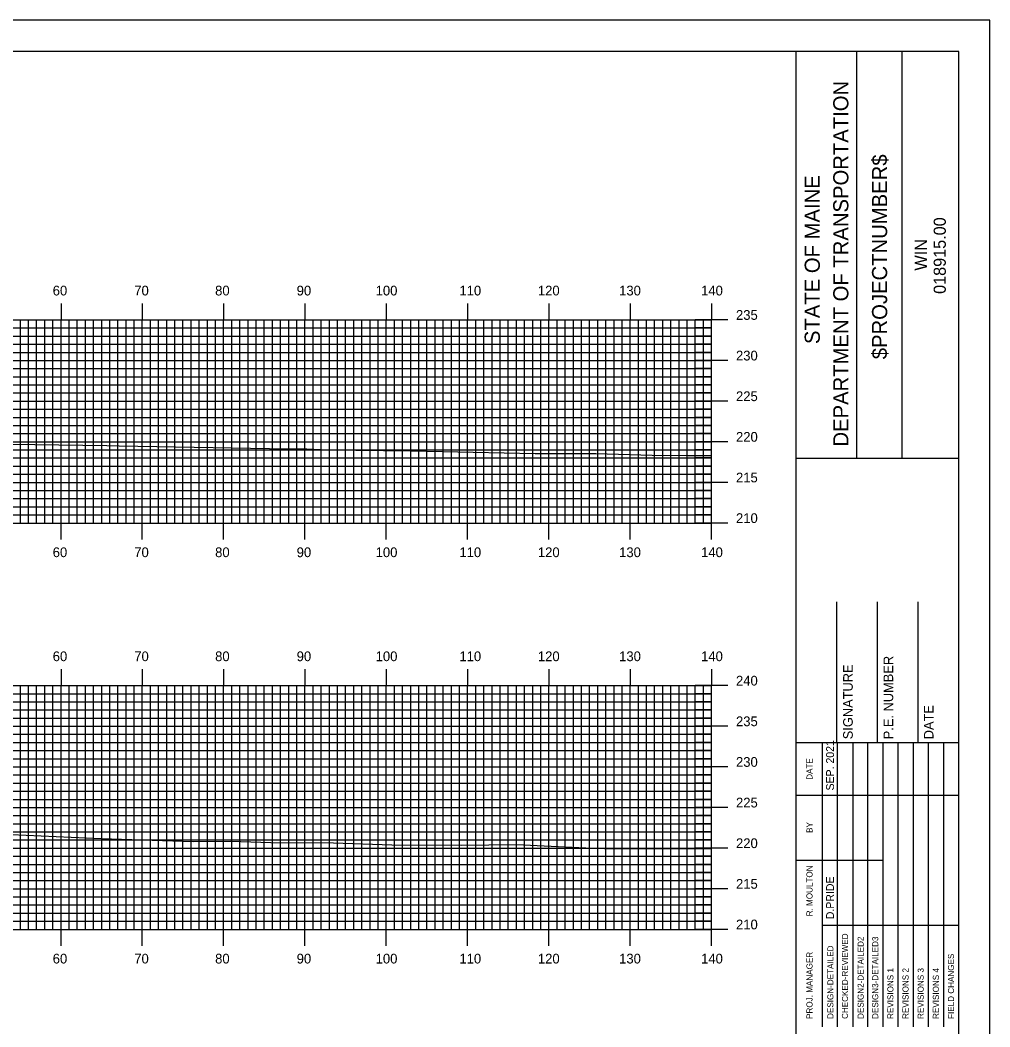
# Model space of a CAD drawing. Extents: x 1803897 to 1804240, y 442591 to 442811.
# Drawn here: x 1804117.6 to 1804236.9, y 442686.7 to 442810.5 of the extents above; entities that cross this region are included whole.
import ezdxf

# ---------------------------------------------------------------- set-up
doc = ezdxf.new("R2010")
doc.units = 0
for name, color, linetype in [('BORDER', 7, 'Continuous'), ('H_V ANNOTATION', 7, 'Continuous'), ('MAJOR', 7, 'Continuous'), ('MINOR', 7, 'Continuous'), ('PLOT BOUNDARY', 7, 'Continuous'), ('S_Roadway_Centerline', 7, 'Continuous')]:
    doc.layers.add(name, color=color, linetype=linetype)

msp = doc.modelspace()

# ---------------------------------------------------------------- linework, layer by layer
at = {"layer": 'BORDER'}
for p, q in [((1804213.05, 442596.67), (1804213.05, 442806.67)), ((1804220.51, 442756.66), (1804220.51, 442806.66)), ((1804226.1, 442756.66), (1804226.1, 442806.66)), ((1804213.06, 442756.65), (1804233.05, 442756.65)), ((1804218.05, 442721.67), (1804218.05, 442738.97)), ((1804223.05, 442721.67), (1804223.05, 442738.97)), ((1804228.05, 442721.67), (1804228.05, 442738.97)), ((1804213.05, 442721.67), (1804233.05, 442721.67))]:
    msp.add_line(p, q, dxfattribs=at)
msp.add_lwpolyline([(1803913.05, 442596.67), (1804233.05, 442596.67), (1804233.05, 442806.67), (1803913.05, 442806.67)], close=True, dxfattribs=at)
for points in [[(1804216.28, 442715.17), (1804216.28, 442721.67)], [(1804218.15, 442686.68), (1804218.15, 442721.67)], [(1804220.01, 442721.67), (1804220.01, 442686.68)], [(1804221.88, 442686.68), (1804221.88, 442721.67)], [(1804223.74, 442686.68), (1804223.74, 442721.67)], [(1804225.6, 442686.68), (1804225.6, 442721.67)], [(1804227.47, 442686.68), (1804227.47, 442721.67)], [(1804229.33, 442686.68), (1804229.33, 442721.67)], [(1804231.19, 442686.68), (1804231.19, 442721.67)], [(1804216.29, 442686.68), (1804216.29, 442720.26)], [(1804213.05, 442715.17), (1804233.05, 442715.17)], [(1804213.05, 442707.17), (1804216.29, 442707.17)], [(1804216.28, 442707.17), (1804223.74, 442707.17)], [(1804216.28, 442699.17), (1804233.05, 442699.17)]]:
    msp.add_lwpolyline(points, dxfattribs=at)
at = {"layer": 'MAJOR'}
for p, q in [((1804122.65, 442775.67), (1804122.65, 442773.67)), ((1804132.65, 442775.67), (1804132.65, 442773.67)), ((1804142.65, 442775.67), (1804142.65, 442773.67)), ((1804152.65, 442775.67), (1804152.65, 442773.67)), ((1804162.65, 442775.67), (1804162.65, 442773.67)), ((1804172.65, 442775.67), (1804172.65, 442773.67)), ((1804182.65, 442775.67), (1804182.65, 442773.67)), ((1804192.65, 442775.67), (1804192.65, 442773.67)), ((1804202.65, 442775.67), (1804202.65, 442773.67)), ((1803922.65, 442773.67), (1804202.65, 442773.67)), ((1803922.65, 442773.67), (1804202.65, 442773.67)), ((1804122.65, 442748.67), (1804122.65, 442773.67)), ((1804132.65, 442748.67), (1804132.65, 442773.67)), ((1804142.65, 442748.67), (1804142.65, 442773.67)), ((1804152.65, 442748.67), (1804152.65, 442773.67)), ((1804162.65, 442748.67), (1804162.65, 442773.67)), ((1804172.65, 442748.67), (1804172.65, 442773.67)), ((1804182.65, 442748.67), (1804182.65, 442773.67)), ((1804192.65, 442748.67), (1804192.65, 442773.67)), ((1804204.66, 442773.67), (1804200.65, 442773.67)), ((1804202.65, 442748.67), (1804202.65, 442773.67)), ((1804202.65, 442748.67), (1804202.65, 442773.67)), ((1803922.65, 442768.67), (1804202.65, 442768.67)), ((1804204.66, 442768.67), (1804200.65, 442768.67)), ((1803922.65, 442763.67), (1804202.65, 442763.67)), ((1804204.66, 442763.67), (1804200.65, 442763.67)), ((1803922.65, 442758.67), (1804202.65, 442758.67)), ((1804204.66, 442758.67), (1804200.65, 442758.67)), ((1803922.65, 442753.67), (1804202.65, 442753.67)), ((1804204.66, 442753.67), (1804200.65, 442753.67)), ((1803922.65, 442748.67), (1804202.65, 442748.67)), ((1803922.65, 442748.67), (1804202.65, 442748.67)), ((1804122.65, 442746.66), (1804122.65, 442748.67)), ((1804132.65, 442746.66), (1804132.65, 442748.67)), ((1804142.65, 442746.66), (1804142.65, 442748.67)), ((1804152.65, 442746.66), (1804152.65, 442748.67)), ((1804162.65, 442746.66), (1804162.65, 442748.67)), ((1804172.65, 442746.66), (1804172.65, 442748.67)), ((1804182.65, 442746.66), (1804182.65, 442748.67)), ((1804192.65, 442746.66), (1804192.65, 442748.67)), ((1804204.66, 442748.67), (1804200.65, 442748.67)), ((1804202.65, 442746.66), (1804202.65, 442748.67)), ((1804122.65, 442730.67), (1804122.65, 442728.67)), ((1804132.65, 442730.67), (1804132.65, 442728.67)), ((1804142.65, 442730.67), (1804142.65, 442728.67)), ((1804152.65, 442730.67), (1804152.65, 442728.67)), ((1804162.65, 442730.67), (1804162.65, 442728.67)), ((1804172.65, 442730.67), (1804172.65, 442728.67)), ((1804182.65, 442730.67), (1804182.65, 442728.67)), ((1804192.65, 442730.67), (1804192.65, 442728.67)), ((1804202.65, 442730.67), (1804202.65, 442728.67)), ((1803922.65, 442728.67), (1804202.65, 442728.67)), ((1803922.65, 442728.67), (1804202.65, 442728.67)), ((1804122.65, 442698.67), (1804122.65, 442728.67)), ((1804132.65, 442698.67), (1804132.65, 442728.67)), ((1804142.65, 442698.67), (1804142.65, 442728.67)), ((1804152.65, 442698.67), (1804152.65, 442728.67)), ((1804162.65, 442698.67), (1804162.65, 442728.67)), ((1804172.65, 442698.67), (1804172.65, 442728.67)), ((1804182.65, 442698.67), (1804182.65, 442728.67)), ((1804192.65, 442698.67), (1804192.65, 442728.67)), ((1804204.66, 442728.67), (1804200.65, 442728.67)), ((1804202.65, 442698.67), (1804202.65, 442728.67)), ((1804202.65, 442698.67), (1804202.65, 442728.67)), ((1803922.65, 442723.67), (1804202.65, 442723.67)), ((1804204.66, 442723.67), (1804200.65, 442723.67)), ((1803922.65, 442718.67), (1804202.65, 442718.67)), ((1804204.66, 442718.67), (1804200.65, 442718.67)), ((1803922.65, 442713.67), (1804202.65, 442713.67)), ((1804204.66, 442713.67), (1804200.65, 442713.67)), ((1803922.65, 442708.67), (1804202.65, 442708.67)), ((1804204.66, 442708.67), (1804200.65, 442708.67)), ((1803922.65, 442703.67), (1804202.65, 442703.67)), ((1804204.66, 442703.67), (1804200.65, 442703.67)), ((1803922.65, 442698.67), (1804202.65, 442698.67)), ((1803922.65, 442698.67), (1804202.65, 442698.67)), ((1804122.65, 442696.66), (1804122.65, 442698.67)), ((1804132.65, 442696.66), (1804132.65, 442698.67)), ((1804142.65, 442696.66), (1804142.65, 442698.67)), ((1804152.65, 442696.66), (1804152.65, 442698.67)), ((1804162.65, 442696.66), (1804162.65, 442698.67)), ((1804172.65, 442696.66), (1804172.65, 442698.67)), ((1804182.65, 442696.66), (1804182.65, 442698.67)), ((1804192.65, 442696.66), (1804192.65, 442698.67)), ((1804204.66, 442698.67), (1804200.65, 442698.67)), ((1804202.65, 442696.66), (1804202.65, 442698.67))]:
    msp.add_line(p, q, dxfattribs=at)
at = {"layer": 'MINOR'}
for p, q in [((1804117.65, 442748.67), (1804117.65, 442773.67)), ((1804118.65, 442748.67), (1804118.65, 442773.67)), ((1804119.65, 442748.67), (1804119.65, 442773.67)), ((1804120.65, 442748.67), (1804120.65, 442773.67)), ((1804121.65, 442748.67), (1804121.65, 442773.67)), ((1804123.65, 442748.67), (1804123.65, 442773.67)), ((1804124.65, 442748.67), (1804124.65, 442773.67)), ((1804125.65, 442748.67), (1804125.65, 442773.67)), ((1804126.65, 442748.67), (1804126.65, 442773.67)), ((1804127.65, 442748.67), (1804127.65, 442773.67)), ((1804128.65, 442748.67), (1804128.65, 442773.67)), ((1804129.65, 442748.67), (1804129.65, 442773.67)), ((1804130.65, 442748.67), (1804130.65, 442773.67)), ((1804131.65, 442748.67), (1804131.65, 442773.67)), ((1804133.65, 442748.67), (1804133.65, 442773.67)), ((1804134.65, 442748.67), (1804134.65, 442773.67)), ((1804135.65, 442748.67), (1804135.65, 442773.67)), ((1804136.65, 442748.67), (1804136.65, 442773.67)), ((1804137.65, 442748.67), (1804137.65, 442773.67)), ((1804138.65, 442748.67), (1804138.65, 442773.67)), ((1804139.65, 442748.67), (1804139.65, 442773.67)), ((1804140.65, 442748.67), (1804140.65, 442773.67)), ((1804141.65, 442748.67), (1804141.65, 442773.67)), ((1804143.65, 442748.67), (1804143.65, 442773.67)), ((1804144.65, 442748.67), (1804144.65, 442773.67)), ((1804145.65, 442748.67), (1804145.65, 442773.67)), ((1804146.65, 442748.67), (1804146.65, 442773.67)), ((1804147.65, 442748.67), (1804147.65, 442773.67)), ((1804148.65, 442748.67), (1804148.65, 442773.67)), ((1804149.65, 442748.67), (1804149.65, 442773.67)), ((1804150.65, 442748.67), (1804150.65, 442773.67)), ((1804151.65, 442748.67), (1804151.65, 442773.67)), ((1804153.65, 442748.67), (1804153.65, 442773.67)), ((1804154.65, 442748.67), (1804154.65, 442773.67)), ((1804155.65, 442748.67), (1804155.65, 442773.67)), ((1804156.65, 442748.67), (1804156.65, 442773.67)), ((1804157.65, 442748.67), (1804157.65, 442773.67)), ((1804158.65, 442748.67), (1804158.65, 442773.67)), ((1804159.65, 442748.67), (1804159.65, 442773.67)), ((1804160.65, 442748.67), (1804160.65, 442773.67)), ((1804161.65, 442748.67), (1804161.65, 442773.67)), ((1804163.65, 442748.67), (1804163.65, 442773.67)), ((1804164.65, 442748.67), (1804164.65, 442773.67)), ((1804165.65, 442748.67), (1804165.65, 442773.67)), ((1804166.65, 442748.67), (1804166.65, 442773.67)), ((1804167.65, 442748.67), (1804167.65, 442773.67)), ((1804168.65, 442748.67), (1804168.65, 442773.67)), ((1804169.65, 442748.67), (1804169.65, 442773.67)), ((1804170.65, 442748.67), (1804170.65, 442773.67)), ((1804171.65, 442748.67), (1804171.65, 442773.67)), ((1804173.65, 442748.67), (1804173.65, 442773.67)), ((1804174.65, 442748.67), (1804174.65, 442773.67)), ((1804175.65, 442748.67), (1804175.65, 442773.67)), ((1804176.65, 442748.67), (1804176.65, 442773.67)), ((1804177.65, 442748.67), (1804177.65, 442773.67)), ((1804178.65, 442748.67), (1804178.65, 442773.67)), ((1804179.65, 442748.67), (1804179.65, 442773.67)), ((1804180.65, 442748.67), (1804180.65, 442773.67)), ((1804181.65, 442748.67), (1804181.65, 442773.67)), ((1804183.65, 442748.67), (1804183.65, 442773.67)), ((1804184.65, 442748.67), (1804184.65, 442773.67)), ((1804185.65, 442748.67), (1804185.65, 442773.67)), ((1804186.65, 442748.67), (1804186.65, 442773.67)), ((1804187.65, 442748.67), (1804187.65, 442773.67)), ((1804188.65, 442748.67), (1804188.65, 442773.67)), ((1804189.65, 442748.67), (1804189.65, 442773.67)), ((1804190.65, 442748.67), (1804190.65, 442773.67)), ((1804191.65, 442748.67), (1804191.65, 442773.67)), ((1804193.65, 442748.67), (1804193.65, 442773.67)), ((1804194.65, 442748.67), (1804194.65, 442773.67)), ((1804195.65, 442748.67), (1804195.65, 442773.67)), ((1804196.65, 442748.67), (1804196.65, 442773.67)), ((1804197.65, 442748.67), (1804197.65, 442773.67)), ((1804198.65, 442748.67), (1804198.65, 442773.67)), ((1804199.65, 442748.67), (1804199.65, 442773.67)), ((1804200.65, 442748.67), (1804200.65, 442773.67)), ((1804201.65, 442748.67), (1804201.65, 442773.67)), ((1803922.65, 442772.67), (1804202.65, 442772.67)), ((1804202.65, 442772.67), (1804200.65, 442772.67)), ((1803922.65, 442771.67), (1804202.65, 442771.67)), ((1804202.65, 442771.67), (1804200.65, 442771.67)), ((1803922.65, 442770.67), (1804202.65, 442770.67)), ((1804202.65, 442770.67), (1804200.65, 442770.67)), ((1803922.65, 442769.67), (1804202.65, 442769.67)), ((1804202.65, 442769.67), (1804200.65, 442769.67)), ((1803922.65, 442767.67), (1804202.65, 442767.67)), ((1804202.65, 442767.67), (1804200.65, 442767.67)), ((1803922.65, 442766.67), (1804202.65, 442766.67)), ((1804202.65, 442766.67), (1804200.65, 442766.67)), ((1803922.65, 442765.67), (1804202.65, 442765.67)), ((1804202.65, 442765.67), (1804200.65, 442765.67)), ((1803922.65, 442764.67), (1804202.65, 442764.67)), ((1804202.65, 442764.67), (1804200.65, 442764.67)), ((1803922.65, 442762.67), (1804202.65, 442762.67)), ((1804202.65, 442762.67), (1804200.65, 442762.67)), ((1803922.65, 442761.67), (1804202.65, 442761.67)), ((1804202.65, 442761.67), (1804200.65, 442761.67)), ((1803922.65, 442760.67), (1804202.65, 442760.67)), ((1804202.65, 442760.67), (1804200.65, 442760.67)), ((1803922.65, 442759.67), (1804202.65, 442759.67)), ((1804202.65, 442759.67), (1804200.65, 442759.67)), ((1803922.65, 442757.67), (1804202.65, 442757.67)), ((1804202.65, 442757.67), (1804200.65, 442757.67)), ((1803922.65, 442756.67), (1804202.65, 442756.67)), ((1804202.65, 442756.67), (1804200.65, 442756.67)), ((1803922.65, 442755.67), (1804202.65, 442755.67)), ((1804202.65, 442755.67), (1804200.65, 442755.67)), ((1803922.65, 442754.67), (1804202.65, 442754.67)), ((1804202.65, 442754.67), (1804200.65, 442754.67)), ((1803922.65, 442752.67), (1804202.65, 442752.67)), ((1804202.65, 442752.67), (1804200.65, 442752.67)), ((1803922.65, 442751.67), (1804202.65, 442751.67)), ((1804202.65, 442751.67), (1804200.65, 442751.67)), ((1803922.65, 442750.67), (1804202.65, 442750.67)), ((1804202.65, 442750.67), (1804200.65, 442750.67)), ((1803922.65, 442749.67), (1804202.65, 442749.67)), ((1804202.65, 442749.67), (1804200.65, 442749.67)), ((1803922.65, 442727.67), (1804202.65, 442727.67)), ((1804117.65, 442698.67), (1804117.65, 442728.67)), ((1804118.65, 442698.67), (1804118.65, 442728.67)), ((1804119.65, 442698.67), (1804119.65, 442728.67)), ((1804120.65, 442698.67), (1804120.65, 442728.67)), ((1804121.65, 442698.67), (1804121.65, 442728.67)), ((1804123.65, 442698.67), (1804123.65, 442728.67)), ((1804124.65, 442698.67), (1804124.65, 442728.67)), ((1804125.65, 442698.67), (1804125.65, 442728.67)), ((1804126.65, 442698.67), (1804126.65, 442728.67)), ((1804127.65, 442698.67), (1804127.65, 442728.67)), ((1804128.65, 442698.67), (1804128.65, 442728.67)), ((1804129.65, 442698.67), (1804129.65, 442728.67)), ((1804130.65, 442698.67), (1804130.65, 442728.67)), ((1804131.65, 442698.67), (1804131.65, 442728.67)), ((1804133.65, 442698.67), (1804133.65, 442728.67)), ((1804134.65, 442698.67), (1804134.65, 442728.67)), ((1804135.65, 442698.67), (1804135.65, 442728.67)), ((1804136.65, 442698.67), (1804136.65, 442728.67)), ((1804137.65, 442698.67), (1804137.65, 442728.67)), ((1804138.65, 442698.67), (1804138.65, 442728.67)), ((1804139.65, 442698.67), (1804139.65, 442728.67)), ((1804140.65, 442698.67), (1804140.65, 442728.67)), ((1804141.65, 442698.67), (1804141.65, 442728.67)), ((1804143.65, 442698.67), (1804143.65, 442728.67)), ((1804144.65, 442698.67), (1804144.65, 442728.67)), ((1804145.65, 442698.67), (1804145.65, 442728.67)), ((1804146.65, 442698.67), (1804146.65, 442728.67)), ((1804147.65, 442698.67), (1804147.65, 442728.67)), ((1804148.65, 442698.67), (1804148.65, 442728.67)), ((1804149.65, 442698.67), (1804149.65, 442728.67)), ((1804150.65, 442698.67), (1804150.65, 442728.67)), ((1804151.65, 442698.67), (1804151.65, 442728.67)), ((1804153.65, 442698.67), (1804153.65, 442728.67)), ((1804154.65, 442698.67), (1804154.65, 442728.67)), ((1804155.65, 442698.67), (1804155.65, 442728.67)), ((1804156.65, 442698.67), (1804156.65, 442728.67)), ((1804157.65, 442698.67), (1804157.65, 442728.67)), ((1804158.65, 442698.67), (1804158.65, 442728.67)), ((1804159.65, 442698.67), (1804159.65, 442728.67)), ((1804160.65, 442698.67), (1804160.65, 442728.67)), ((1804161.65, 442698.67), (1804161.65, 442728.67)), ((1804163.65, 442698.67), (1804163.65, 442728.67)), ((1804164.65, 442698.67), (1804164.65, 442728.67)), ((1804165.65, 442698.67), (1804165.65, 442728.67)), ((1804166.65, 442698.67), (1804166.65, 442728.67)), ((1804167.65, 442698.67), (1804167.65, 442728.67)), ((1804168.65, 442698.67), (1804168.65, 442728.67)), ((1804169.65, 442698.67), (1804169.65, 442728.67)), ((1804170.65, 442698.67), (1804170.65, 442728.67)), ((1804171.65, 442698.67), (1804171.65, 442728.67)), ((1804173.65, 442698.67), (1804173.65, 442728.67)), ((1804174.65, 442698.67), (1804174.65, 442728.67)), ((1804175.65, 442698.67), (1804175.65, 442728.67)), ((1804176.65, 442698.67), (1804176.65, 442728.67)), ((1804177.65, 442698.67), (1804177.65, 442728.67)), ((1804178.65, 442698.67), (1804178.65, 442728.67)), ((1804179.65, 442698.67), (1804179.65, 442728.67)), ((1804180.65, 442698.67), (1804180.65, 442728.67)), ((1804181.65, 442698.67), (1804181.65, 442728.67)), ((1804183.65, 442698.67), (1804183.65, 442728.67)), ((1804184.65, 442698.67), (1804184.65, 442728.67)), ((1804185.65, 442698.67), (1804185.65, 442728.67)), ((1804186.65, 442698.67), (1804186.65, 442728.67)), ((1804187.65, 442698.67), (1804187.65, 442728.67)), ((1804188.65, 442698.67), (1804188.65, 442728.67)), ((1804189.65, 442698.67), (1804189.65, 442728.67)), ((1804190.65, 442698.67), (1804190.65, 442728.67)), ((1804191.65, 442698.67), (1804191.65, 442728.67)), ((1804193.65, 442698.67), (1804193.65, 442728.67)), ((1804194.65, 442698.67), (1804194.65, 442728.67)), ((1804195.65, 442698.67), (1804195.65, 442728.67)), ((1804196.65, 442698.67), (1804196.65, 442728.67)), ((1804197.65, 442698.67), (1804197.65, 442728.67)), ((1804198.65, 442698.67), (1804198.65, 442728.67)), ((1804199.65, 442698.67), (1804199.65, 442728.67)), ((1804200.65, 442698.67), (1804200.65, 442728.67)), ((1804202.65, 442727.67), (1804200.65, 442727.67)), ((1804201.65, 442698.67), (1804201.65, 442728.67)), ((1803922.65, 442726.67), (1804202.65, 442726.67)), ((1804202.65, 442726.67), (1804200.65, 442726.67)), ((1803922.65, 442725.67), (1804202.65, 442725.67)), ((1804202.65, 442725.67), (1804200.65, 442725.67)), ((1803922.65, 442724.67), (1804202.65, 442724.67)), ((1804202.65, 442724.67), (1804200.65, 442724.67)), ((1803922.65, 442722.67), (1804202.65, 442722.67)), ((1803922.65, 442721.67), (1804202.65, 442721.67)), ((1804202.65, 442722.67), (1804200.65, 442722.67)), ((1804202.65, 442721.67), (1804200.65, 442721.67)), ((1803922.65, 442720.67), (1804202.65, 442720.67)), ((1804202.65, 442720.67), (1804200.65, 442720.67)), ((1803922.65, 442719.67), (1804202.65, 442719.67)), ((1804202.65, 442719.67), (1804200.65, 442719.67)), ((1803922.65, 442717.67), (1804202.65, 442717.67)), ((1803922.65, 442716.67), (1804202.65, 442716.67)), ((1804202.65, 442717.67), (1804200.65, 442717.67)), ((1804202.65, 442716.67), (1804200.65, 442716.67)), ((1803922.65, 442715.67), (1804202.65, 442715.67)), ((1804202.65, 442715.67), (1804200.65, 442715.67)), ((1803922.65, 442714.67), (1804202.65, 442714.67)), ((1804202.65, 442714.67), (1804200.65, 442714.67)), ((1803922.65, 442712.67), (1804202.65, 442712.67)), ((1803922.65, 442711.67), (1804202.65, 442711.67)), ((1804202.65, 442712.67), (1804200.65, 442712.67)), ((1804202.65, 442711.67), (1804200.65, 442711.67)), ((1803922.65, 442710.67), (1804202.65, 442710.67)), ((1804202.65, 442710.67), (1804200.65, 442710.67)), ((1803922.65, 442709.67), (1804202.65, 442709.67)), ((1804202.65, 442709.67), (1804200.65, 442709.67)), ((1803922.65, 442707.67), (1804202.65, 442707.67)), ((1803922.65, 442706.67), (1804202.65, 442706.67)), ((1804202.65, 442707.67), (1804200.65, 442707.67)), ((1804202.65, 442706.67), (1804200.65, 442706.67)), ((1803922.65, 442705.67), (1804202.65, 442705.67)), ((1804202.65, 442705.67), (1804200.65, 442705.67)), ((1803922.65, 442704.67), (1804202.65, 442704.67)), ((1804202.65, 442704.67), (1804200.65, 442704.67)), ((1803922.65, 442702.67), (1804202.65, 442702.67)), ((1803922.65, 442701.67), (1804202.65, 442701.67)), ((1804202.65, 442702.67), (1804200.65, 442702.67)), ((1804202.65, 442701.67), (1804200.65, 442701.67)), ((1803922.65, 442700.67), (1804202.65, 442700.67)), ((1804202.65, 442700.67), (1804200.65, 442700.67)), ((1803922.65, 442699.67), (1804202.65, 442699.67)), ((1804202.65, 442699.67), (1804200.65, 442699.67))]:
    msp.add_line(p, q, dxfattribs=at)
at = {"layer": 'PLOT BOUNDARY'}
msp.add_lwpolyline([(1803896.87, 442590.55), (1804236.87, 442590.55), (1804236.87, 442810.55), (1803896.87, 442810.55)], close=True, dxfattribs=at)
at = {"layer": 'S_Roadway_Centerline'}
for points in [[(1804108.12, 442758.51), (1804119.42, 442758.34), (1804128.29, 442758.22), (1804129.8, 442758.18), (1804150.57, 442757.8), (1804152.87, 442757.79), (1804155.46, 442757.69), (1804165.73, 442757.55), (1804173.35, 442757.4), (1804180.97, 442757.24), (1804188.43, 442757.23), (1804195.35, 442757.01), (1804199.78, 442756.99), (1804202.65, 442756.98)], [(1804114.65, 442710.42), (1804127.57, 442709.85), (1804138.89, 442709.47), (1804143.53, 442709.51), (1804148.44, 442709.34), (1804156.15, 442709.32), (1804163.34, 442709.07), (1804171.87, 442709.02), (1804178.66, 442709.11), (1804187.18, 442708.71), (1804190.62, 442708.57), (1804193.65, 442708.62), (1804202.65, 442708.56)]]:
    msp.add_lwpolyline(points, dxfattribs=at)

# ---------------------------------------------------------------- texts
at = {"layer": 'BORDER'}
for s, height, p in [('DEPARTMENT OF TRANSPORTATION', 1.8635, (1804219.47, 442758.08)), ('$PROJECTNUMBER$', 1.8635, (1804224.24, 442768.82)), ('STATE OF MAINE', 1.8635, (1804215.96, 442770.69)), ('018915.00', 1.491, (1804231.45, 442776.86)), ('WIN', 1.491, (1804229.13, 442779.73)), ('P.E. NUMBER', 1.1811, (1804224.98, 442722.06)), ('SIGNATURE', 1.181, (1804220.01, 442722.06)), ('DATE', 1.181, (1804229.94, 442722.06)), ('SEP. 2021', 0.969, (1804217.7, 442715.76)), ('DATE', 0.743, (1804215.06, 442717.08)), ('BY', 0.743, (1804215.06, 442710.54)), ('R. MOULTON', 0.745, (1804215.06, 442700.28)), ('D.PRIDE', 0.969, (1804217.7, 442699.92)), ('CHECKED-REVIEWED', 0.7455, (1804219.42, 442687.65)), ('DESIGN2-DETAILED2', 0.7455, (1804221.35, 442687.65)), ('DESIGN3-DETAILED3', 0.7455, (1804223.14, 442687.65)), ('PROJ. MANAGER', 0.7455, (1804215.06, 442687.65)), ('DESIGN-DETAILED', 0.7455, (1804217.63, 442687.65)), ('FIELD CHANGES', 0.7455, (1804232.46, 442687.65)), ('REVISIONS 1', 0.7455, (1804225.01, 442687.65)), ('REVISIONS 2', 0.7455, (1804226.87, 442687.65)), ('REVISIONS 3', 0.7455, (1804228.73, 442687.65)), ('REVISIONS 4', 0.7455, (1804230.6, 442687.65))]:
    msp.add_text(s, height=height, rotation=90, dxfattribs=at).set_placement(p)
at = {"layer": 'H_V ANNOTATION'}
for s, p in [('60', (1804121.63, 442776.67)), ('70', (1804131.66, 442776.67)), ('80', (1804141.6, 442776.67)), ('90', (1804151.63, 442776.67)), ('100', (1804161.34, 442776.67)), ('110', (1804171.64, 442776.67)), ('120', (1804181.29, 442776.67)), ('130', (1804191.28, 442776.67)), ('140', (1804201.36, 442776.67)), ('235', (1804205.65, 442773.67)), ('230', (1804205.65, 442768.67)), ('225', (1804205.65, 442763.67)), ('220', (1804205.65, 442758.67)), ('215', (1804205.65, 442753.67)), ('210', (1804205.65, 442748.67)), ('60', (1804121.63, 442744.47)), ('70', (1804131.66, 442744.47)), ('80', (1804141.6, 442744.47)), ('90', (1804151.63, 442744.47)), ('100', (1804161.34, 442744.47)), ('110', (1804171.64, 442744.47)), ('120', (1804181.29, 442744.47)), ('130', (1804191.28, 442744.47)), ('140', (1804201.36, 442744.47)), ('60', (1804121.63, 442731.67)), ('70', (1804131.66, 442731.67)), ('80', (1804141.6, 442731.67)), ('90', (1804151.63, 442731.67)), ('100', (1804161.34, 442731.67)), ('110', (1804171.64, 442731.67)), ('120', (1804181.29, 442731.67)), ('130', (1804191.28, 442731.67)), ('140', (1804201.36, 442731.67)), ('240', (1804205.65, 442728.67)), ('235', (1804205.65, 442723.67)), ('230', (1804205.65, 442718.67)), ('225', (1804205.65, 442713.67)), ('220', (1804205.65, 442708.67)), ('215', (1804205.65, 442703.67)), ('210', (1804205.65, 442698.67)), ('60', (1804121.63, 442694.47)), ('70', (1804131.66, 442694.47)), ('80', (1804141.6, 442694.47)), ('90', (1804151.63, 442694.47)), ('100', (1804161.34, 442694.47)), ('110', (1804171.64, 442694.47)), ('120', (1804181.29, 442694.47)), ('130', (1804191.28, 442694.47)), ('140', (1804201.36, 442694.47))]:
    msp.add_text(s, height=1.2, dxfattribs=at).set_placement(p)

doc.saveas('drawing.dxf')
